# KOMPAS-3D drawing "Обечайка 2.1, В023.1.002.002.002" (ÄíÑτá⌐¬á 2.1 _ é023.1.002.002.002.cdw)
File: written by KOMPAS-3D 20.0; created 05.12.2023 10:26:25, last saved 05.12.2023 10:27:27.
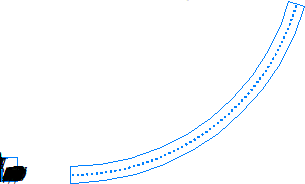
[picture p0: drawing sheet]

Sheet 1: A4, portrait

Document properties: Автор: alg; Масса: 17.6287

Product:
- Part/product: Обечайка 2.1  | designation В023.1.002.002.002
    Масса: 17.6287
    source file: Обечайка 2.1 _ В023.1.002.002.002.cdw

Title block, sheet 1: Наименование: Обечайка 2.1; designation: В023.1.002.002.002; Материал: Сталь 10  ГОСТ 1050-2013; Масса: 17,63; Количество листов документа: 1; Форматы листов документа: A4; stored path: C:\Обечайка 2.1 _ В023.1.002.002.002.cdw

Views: Вид 1, Вид:1, Развертка
Referenced files in C:\: Обечайка 2.1 _ В023.1.002.002.002.m3d
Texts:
  В023.1.002.002.002 Обечайка 2.1
Dimensions and other numbers on the sheet: 1:1; 1; 17,63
